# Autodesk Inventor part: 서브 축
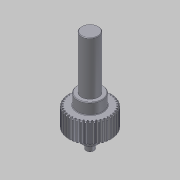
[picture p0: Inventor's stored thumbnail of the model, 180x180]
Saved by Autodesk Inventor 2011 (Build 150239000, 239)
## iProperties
Created: 2014-07
Part Number: 서브 축
Material: Steel
Document SubType Name: Modeling
Designer: KYOUNG IL JANG
Categories: <?xml version="1.0" encoding="UTF-16"?> <MemberInstance><Categories><FamilyTemplate><FamilyTemplateParameter ValueType="xs:double" Id="1" ObjectReferenceKey="da
Density: 1 g/cm^3
CustomPartVersion: 1
Company: 한국ATC센터
Author: KYOUNG IL JANG
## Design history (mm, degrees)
sketch "Sketch1"
  geometry: C1 r 21 at (0, 0)
  constraints: 1 centre point
  dimensions: "d0" = 42 diameter of C1 (= da_da)
extrude "Extrusion1" new body sketch "Sketch1" distance "d1" = 20 (= da_b); taper "d2" = 0 deg
workplane "Work Plane2"
sketch "Sketch2"
  geometry: C1 r 21 at (0, 0) reference; C2 r 20 at (0, 0)
  constraints: 1 centre point, 1 coincident
  dimensions: "d3" = 40 diameter of C2 (= da_dw)
feature "피치 지름" sketch "Sketch2" dims "d4" = 10, "d5" = 0
workplane "Work Plane8"
workplane "Work Plane9"
chamfer "모따기1" distance "d49" = 1; stored, may be unused: second distance "d50" = 2, angle "d51" = 45 deg
sketch "스케치3"
  geometry: C1 r 12.5 at (0, 0); 1 further point
  constraints: 1 centre point, 1 coincident
  dimensions: "d52" = 25 diameter of C1
extrude "돌출2" join sketch "스케치3" distance "d53" = 11; taper "d54" = 0 deg
sketch "스케치4"
  geometry: C1 r 8.5 at (0, 0); 1 further point
  constraints: 1 centre point, 1 coincident
  dimensions: "d55" = 17 diameter of C1
extrude "돌출3" join sketch "스케치4" distance "d56" = 53; taper "d57" = 0 deg
sketch "스케치5"
  geometry: C1 r 7.5 at (0, 0); 1 further point
  constraints: 1 centre point, 1 coincident
  dimensions: "d62" = 15 diameter of C1
extrude "돌출4" join sketch "스케치5" distance "d63" = 11; taper "d64" = 0 deg
sketch "스케치6"
  geometry: C1 r 4 at (0, 0); 1 further point
  constraints: 1 centre point, 1 coincident
  dimensions: "d65" = 8 diameter of C1
extrude "돌출5" join sketch "스케치6" distance "d66" = 7; taper "d67" = 0 deg
chamfer "모따기2" distance "d58" = 0.5; stored, may be unused: second distance "d59" = 2, angle "d60" = 45 deg
fillet "모깎기1" dims "d61" = 0.5
feature "스퍼 기어" dims "da_b" = 20, "da_d" = 40, "da_aw" = 31, "da_da" = 42, "da_df" = 37.5, "da_dw" = 40, angle "da_beta" = 0 deg, "da_lefttooth" = 0, "da_righttooth" = 0
body "Solid1"
body "Srf1"
other parameters: "d16" = 31 (= da_aw), "d17" = 0, "d34" = 4.5 deg (computed from da_z), "d39" = 0, "d41" = 0, "d43" = 31 (= da_aw), "d46" = 31 (= da_aw), "d47" = 0, "d48" = 0
